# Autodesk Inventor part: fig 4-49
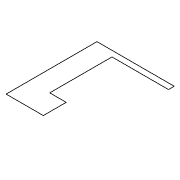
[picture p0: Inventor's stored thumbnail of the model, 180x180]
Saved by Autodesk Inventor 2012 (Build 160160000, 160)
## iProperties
Created: 2004-05
Part Number: fig 4-49
Document SubType Name: Modeling
Designer: CADCIM Technologies
Manufacturer: Standard
Standards Organization: Custom
Density: 1 g/cm^3
Material: Default
Author: CADCIM Technologies
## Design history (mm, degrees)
sketch "Sketch1"
  geometry: L1 (37.08, 12.209)-(23.643, 12.209); L2 (23.643, 12.209)-(23.643, 45.026); L3 (23.643, 45.026)-(51.55, 45.026); L4 (51.55, 45.026)-(51.55, 42.959); L5 (51.55, 42.959)-(31.137, 42.959); L6 (31.137, 42.959)-(31.137, 20.478); L7 (31.137, 20.478)-(37.08, 20.478); L8 (37.08, 20.478)-(37.08, 12.209)
  constraints: 16 end point, 6 parallel, 1 horizontal, 1 perpendicular, 1 other
